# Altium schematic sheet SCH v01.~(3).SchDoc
size A3; SheetNumber: 1; SheetTotal: 1
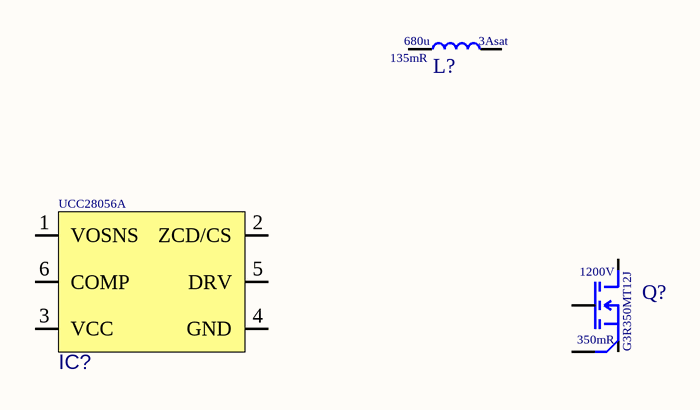
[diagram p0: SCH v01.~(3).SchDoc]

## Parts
IC?  UCC28056A  [SOT-23-6]
L?  Resistance: 135mR  Saturation current: 3Asat  Inductance: 680u  [60B684C]  (hidden comment: Inductor)
Q?  Manufacturer Part Number: G3R350MT12J  Rds: 350mR  Voltage: 1200V  [TO-263-7 D2PAK]  (hidden comment: Nmos_KS)

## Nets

Not connected (* = marked no-connect by the designer): IC? 1(VOSNS) 2(ZCD/CS) 3(VCC) 4(GND) 5(DRV) 6(COMP); L? 1 2; Q? D G KS S

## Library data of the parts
IC? = UCC28056A: PFC TM IC; Manufacturer: Texas Instruments
L? = Inductor: Generic Inductor symbol; Manufacturer: Murata
Q? = Nmos_KS: Generic Nmos symbol with Kelvin Source; Manufacturer: GeneSiC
